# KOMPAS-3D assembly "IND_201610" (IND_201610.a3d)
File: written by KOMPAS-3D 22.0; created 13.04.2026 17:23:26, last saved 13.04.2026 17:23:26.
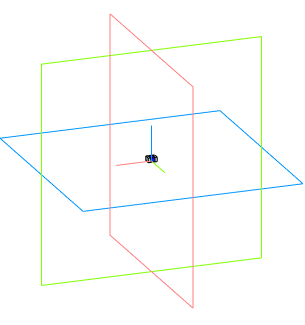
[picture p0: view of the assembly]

Document properties: Автор: Andrey; Полное имя файла: C:\Users\User1\Documents\IND_201610.a3d

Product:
- Component [assembly]: ASSEMBLY  | qty 1  | source file: ASSEMBLY_1.a3d
- Part/product: IND_201610
    Комментарий: IND_201610

Referenced files in C:\Users\User1\Documents\: ASSEMBLY_1.a3d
